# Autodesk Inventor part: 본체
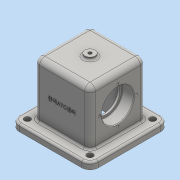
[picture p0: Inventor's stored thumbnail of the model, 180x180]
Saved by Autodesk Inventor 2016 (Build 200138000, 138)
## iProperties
Created: 2022-07
Part Number: 본체
Material: 일반
Document SubType Name: Modeling
Designer: PC-1-6
Density: 1 g/cm^3
Appearance: 기본값
Author: PC-1-6
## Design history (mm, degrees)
sketch "스케치1"
  geometry: L1 (-58, -58)-(58, -58); L2 (58, -58)-(58, 58); L3 (58, 58)-(-58, 58); L4 (-58, 58)-(-58, -58); L5 (-58, -58)-(58, 58); L6 (58, -58)-(-58, 58); 1 further point
  constraints: 12 end point, 2 midpoint, 2 parallel, 1 horizontal, 1 perpendicular
  dimensions: "d0" = 116 distance between parallel lines of L3 L1; "d1" = 116 distance between parallel lines of L2 L4
extrude "돌출1" new body sketch "스케치1" distance "d2" = 10; taper "d3" = 0 deg
sketch "스케치2"
  geometry: L1 (-41, -41)-(41, -41); L2 (41, -41)-(41, 41); L3 (41, 41)-(-41, 41); L4 (-41, 41)-(-41, -41); L5 (-41, -41)-(41, 41); L6 (41, -41)-(-41, 41); 1 further point
  constraints: 12 end point, 2 midpoint, 2 parallel, 1 horizontal, 1 perpendicular
  dimensions: "d4" = 82 distance between parallel lines of L3 L1; "d5" = 82 distance between parallel lines of L2 L4
extrude "돌출2" join sketch "스케치2" distance "d6" = 80; taper "d7" = 0 deg
sketch "스케치3"
  geometry: L1 (21, -30)-(-21, -30); L2 (-21, -30)-(-21, 30); L3 (-21, 30)-(21, 30); L4 (21, 30)-(21, -30); L5 (21, -30)-(-21, 30); L6 (-21, -30)-(21, 30); 1 further point
  constraints: 12 end point, 2 midpoint, 2 parallel, 1 horizontal, 1 perpendicular
  dimensions: "d8" = 60 distance between parallel lines of L3 L1; "d9" = 42 distance between parallel lines of L4 L2
extrude "돌출3" cut sketch "스케치3" distance "d10" = 80; taper "d11" = 0 deg
sketch "스케치4"
  geometry: L1 (41, 10)-(41, 90) reference; L2 (41, 48)-(41, 71.5); L3 (41, 71.5)-(24, 71.5); L4 (24, 71.5)-(24, 68); L5 (24, 68)-(-24, 68); L6 (-24, 68)-(-24, 71.5); L7 (41, 48)-(-41, 48); L8 (-21, 0)-(21, 0) reference; L9 (-24, 71.5)-(-41, 71.5); L10 (-41, 10)-(-41, 90) reference; L11 (-41, 71.5)-(-41, 48); 1 further point
  constraints: 16 end point, 4 perpendicular, 4 point on line, 2 horizontal
  dimensions: "d12" = 48 distance between parallel lines of L7 L8; "d13" = 17 distance between parallel lines of L4 L1; "d14" = 17 distance between parallel lines of L10 L6; "d15" = 47 diameter of L3 L7; "d16" = 40 diameter of L5 L7
revolve "회전1" sketch "스케치4" stored, may be unused: angle "d17" = 90 deg
node "작업 평면1"
sketch "스케치5"
  geometry: C1 r 7.5 at (0, 0); 1 further point
  constraints: 1 centre point, 1 coincident
  dimensions: "d19" = 15 diameter of C1
extrude "돌출4" join sketch "스케치5" stored distance "d20" = 80; taper "d21" = 0 deg
fillet "모깎기1" dims "d22" = 12
fillet "모깎기2" dims "d23" = 8
fillet "모깎기3" dims "d24" = 3
hole "구멍1" diameter "d27" = 9; stored, may be unused: countersink angle "d31" = 90 deg, drill point angle "d33" = 0 deg; dims "d25" = 10, "d26" = 10, "d28" = 6, "d29" = 4, "d30" = 2, "d32" = 8
hole "구멍2" diameter "d36" = 9; stored, may be unused: countersink angle "d40" = 90 deg, drill point angle "d42" = 0 deg; dims "d34" = 10, "d35" = 10, "d37" = 6, "d38" = 4, "d39" = 2, "d41" = 8
hole "구멍3" diameter "d45" = 9; stored, may be unused: countersink angle "d49" = 90 deg, drill point angle "d51" = 0 deg; dims "d43" = 10, "d44" = 10, "d46" = 6, "d47" = 4, "d48" = 2, "d50" = 8
hole "구멍4" diameter "d54" = 9; stored, may be unused: countersink angle "d58" = 90 deg, drill point angle "d60" = 0 deg; dims "d52" = 10, "d53" = 10, "d55" = 6, "d56" = 4, "d57" = 2, "d59" = 8
fillet "모깎기4" dims "d61" = 3
hole "구멍7" diameter "d85" = 4.917; stored, may be unused: countersink angle "d89" = 90 deg, drill point angle "d91" = 118 deg; dims "d83" = 10, "d84" = 10, "d86" = 12, "d87" = 4, "d88" = 2, "d90" = 17.1
fillet "모깎기5" dims "d92" = 3
fillet "모깎기6" dims "d93" = 3
chamfer "모따기1" distance "d94" = 1; stored, may be unused: second distance "d95" = 2, angle "d96" = 45 deg
fillet "모깎기7" dims "d97" = 0.6
fillet "모깎기8" dims "d98" = 3
fillet "모깎기9" dims "d105" = 8
sketch "스케치9" dims "d106" = 54
  geometry: C1 r 24.5 at (-35, 33) reference; 3 further points
  constraints: 2 horizontal alignment, 3 other
hole "구멍8" sketch "스케치9" at (-62, 33) diameter "d107" = 3.242; stored, may be unused: countersink angle "d111" = 90 deg, drill point angle "d113" = 118 deg; dims "d108" = 8, "d109" = 4, "d110" = 2, "d112" = 10
sketch "스케치10"
  geometry: C1 r 1.621 at (62, 33) reference; 2 further points
  constraints: 1 coincident
hole "구멍9" sketch "스케치10" at (62, 33) diameter "d117" = 3.242; stored, may be unused: countersink angle "d121" = 90 deg, drill point angle "d123" = 118 deg; dims "d118" = 8, "d119" = 4, "d120" = 2, "d122" = 10
node "솔리드1"
pattern_circular "원형 패턴3" dims angle "d115" = 360 deg
pattern_circular "원형 패턴4" dims angle "d125" = 360 deg
feature "엠보싱1" dims "d0" = 116, "d1" = 116, "d8" = 60, "d9" = 42, "d132" = 0.5, "d133" = 0
sketch "스케치11"
  geometry: L1 (13, 38)-(53, 38); L2 (53, 38)-(53, 32); L3 (53, 32)-(13, 32); L4 (13, 32)-(13, 38); L5 (13, 35)-(53, 35); L6 (33, 38)-(33, 32); L7 (-13, -13)-(79, -13) reference; L8 (-8, 69)-(-8, 0) reference; 1 further point
  constraints: 4 end point, 4 midpoint, 2 other
  dimensions: "d128" = 40 distance between parallel lines of L2 L4; "d129" = 6 distance between parallel lines of L3 L1; "d130" = 48 distance between parallel lines of L7 L5; "d131" = 41 distance between parallel lines of L8 L6
other parameters: "d18" = 4
